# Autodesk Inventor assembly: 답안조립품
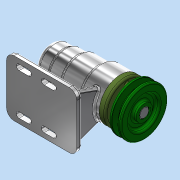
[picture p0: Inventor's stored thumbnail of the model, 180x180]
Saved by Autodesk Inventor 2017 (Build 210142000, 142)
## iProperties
Part Number: 답안조립품
Material: 일반
Document SubType Name: Assembly
Designer: MRC
Author: MRC
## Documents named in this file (12)
- C:\Users\MRC\Desktop\711009V1005\답안조립품.iam
- C:\Users\MRC\Desktop\711009V1005\본체.ipt
- C:\Users\MRC\Desktop\711009V1005\V벨트풀리.ipt
- C:\Users\MRC\Desktop\711009V1005\멈춤나사 M3.ipt
- C:\Users\MRC\Desktop\711009V1005\베어링 6004.ipt
- C:\Users\MRC\Desktop\711009V1005\베어링 51202.ipt
- C:\Users\MRC\Desktop\711009V1005\볼트 M4.ipt
- C:\Users\MRC\Desktop\711009V1005\어댑터슬리브.ipt
- C:\Users\MRC\Desktop\711009V1005\오일 실 20x35x7.ipt
- C:\Users\MRC\Desktop\711009V1005\축.ipt
- C:\Users\MRC\Desktop\711009V1005\커버.ipt
- C:\Users\MRC\Desktop\711009V1005\키 5x5.ipt
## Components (1 placed, 1 different names)
1. V벨트풀리:1
